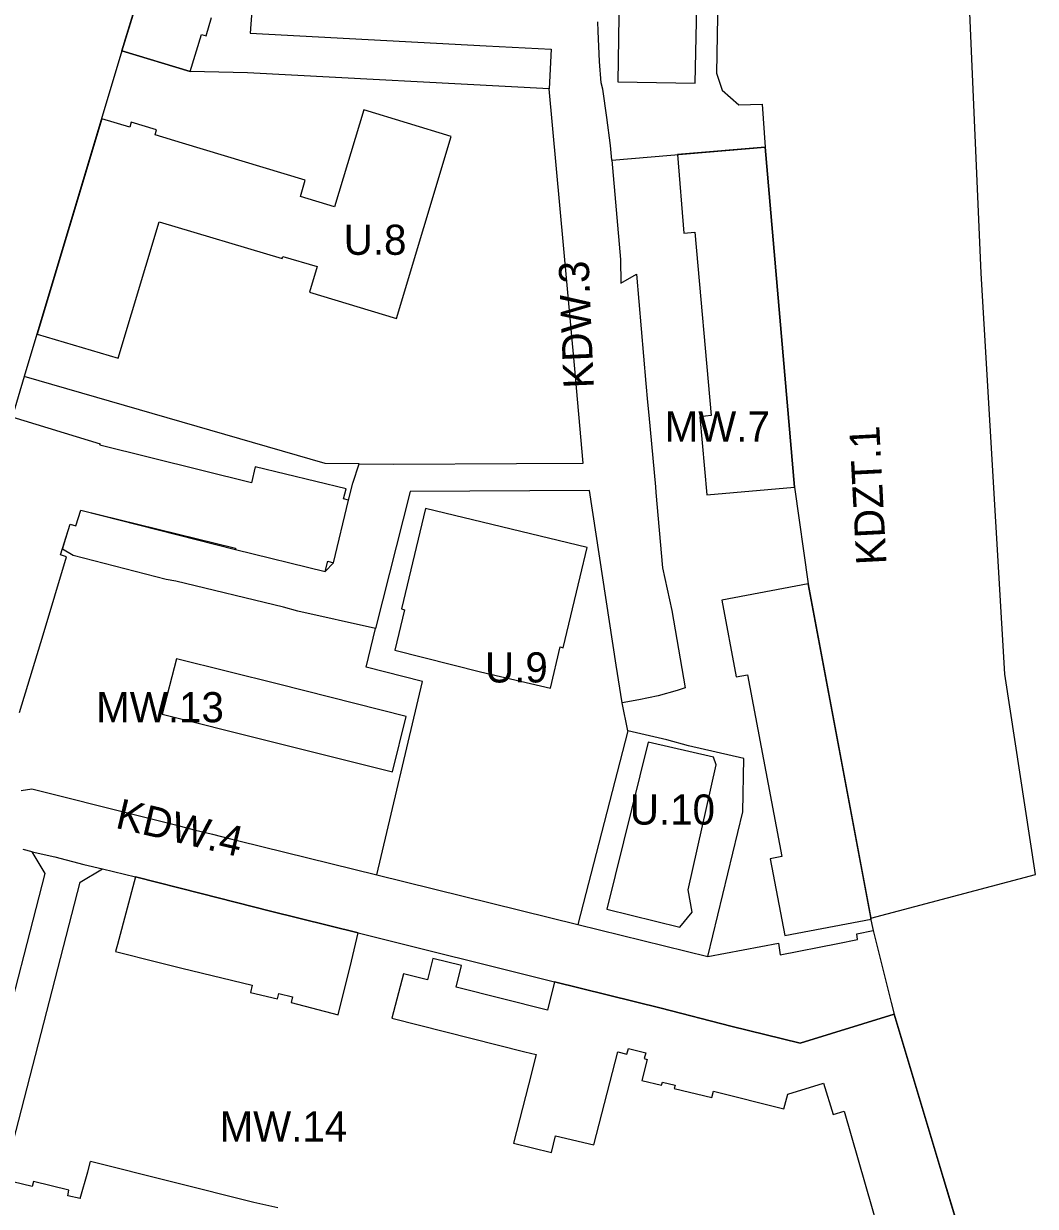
# Model space of a CAD drawing. Extents: x 7424052 to 7425705, y 5546602 to 5547569.
# Drawn here: x 7425299.9 to 7425467.7, y 5547085.1 to 5547281.2 of the extents above; entities that cross this region are included whole.
import ezdxf

# ---------------------------------------------------------------- set-up
doc = ezdxf.new("R2010")
doc.units = 0
for name, color, linetype in [('linie rozgraniczające', 7, 'Continuous'), ('nieprzekraczalne linie zabudowy', 7, 'Continuous'), ('obowiazujace linie zabudowy', 7, 'Continuous'), ('przeznaczenia terenów', 7, 'Continuous')]:
    doc.layers.add(name, color=color, linetype=linetype)

msp = doc.modelspace()

# ---------------------------------------------------------------- linework, layer by layer
at = {"layer": 'linie rozgraniczające'}
for p, q in [((7425415.3, 5547303.98), (7425414.81, 5547272.98)), ((7425458.68, 5547239.81), (7425456.07, 5547299.57)), ((7425316.21, 5547276.67), (7425320.91, 5547292.15)), ((7425338.05, 5547287.8), (7425337.46, 5547279.59)), ((7425395.16, 5547279.91), (7425395.12, 5547281.49)), ((7425337.46, 5547279.59), (7425357.04, 5547278.55)), ((7425395.38, 5547274.88), (7425395.16, 5547279.91)), ((7425357.04, 5547278.55), (7425376.62, 5547277.51)), ((7425376.62, 5547277.51), (7425387.4, 5547276.93)), ((7425316.21, 5547276.67), (7425299.97, 5547222.7)), ((7425327.5, 5547273.25), (7425316.21, 5547276.67)), ((7425387.4, 5547276.93), (7425387.04, 5547270.36)), ((7425337.05, 5547273.02), (7425327.5, 5547273.25)), ((7425395.7, 5547271.39), (7425395.38, 5547274.88)), ((7425387.04, 5547270.36), (7425337.05, 5547273.02)), ((7425395.96, 5547270.3), (7425395.7, 5547271.39)), ((7425414.81, 5547272.98), (7425415.74, 5547270.16)), ((7425391.23, 5547224.55), (7425387.04, 5547270.36)), ((7425396.59, 5547265.64), (7425395.96, 5547270.3)), ((7425415.74, 5547270.16), (7425418.49, 5547267.7)), ((7425418.49, 5547267.7), (7425422.39, 5547267.81)), ((7425422.39, 5547267.81), (7425422.85, 5547260.69)), ((7425397.22, 5547260.99), (7425396.59, 5547265.64)), ((7425397.43, 5547258.56), (7425397.22, 5547260.99)), ((7425397.43, 5547258.56), (7425422.85, 5547260.69)), ((7425422.85, 5547260.69), (7425427.73, 5547204.35)), ((7425397.43, 5547258.56), (7425398.88, 5547242.07)), ((7425398.88, 5547242.07), (7425398.96, 5547238.14)), ((7425462.6, 5547173.31), (7425458.68, 5547239.81)), ((7425398.96, 5547238.14), (7425401.52, 5547239.64)), ((7425401.52, 5547239.64), (7425403.11, 5547221.51)), ((7425392.71, 5547208.29), (7425391.23, 5547224.55)), ((7425299.97, 5547222.7), (7425297.97, 5547215.91)), ((7425349.9, 5547208.27), (7425299.97, 5547222.7)), ((7425403.11, 5547221.51), (7425403.37, 5547218.42)), ((7425403.37, 5547218.42), (7425403.57, 5547216.26)), ((7425403.57, 5547216.26), (7425404.68, 5547204.38)), ((7425355.56, 5547208.2), (7425349.9, 5547208.27)), ((7425354.52, 5547204.97), (7425355.56, 5547208.2)), ((7425355.56, 5547208.2), (7425361.22, 5547208.13)), ((7425361.22, 5547208.13), (7425381.62, 5547208.22)), ((7425381.62, 5547208.22), (7425392.71, 5547208.29)), ((7425353.79, 5547202.16), (7425354.52, 5547204.97)), ((7425364.02, 5547203.61), (7425358.27, 5547180.87)), ((7425393.75, 5547203.76), (7425364.02, 5547203.61)), ((7425398.18, 5547174.83), (7425393.75, 5547203.76)), ((7425404.68, 5547204.38), (7425404.75, 5547203.42)), ((7425404.75, 5547203.42), (7425405.85, 5547190.96)), ((7425427.73, 5547204.35), (7425430.02, 5547188.31)), ((7425351.26, 5547191.8), (7425353.79, 5547202.16)), ((7425308.58, 5547197.9), (7425309.4, 5547200.52)), ((7425309.4, 5547200.52), (7425335.02, 5547194)), ((7425306.32, 5547194.06), (7425307.27, 5547197.12)), ((7425307.27, 5547197.12), (7425307.59, 5547198.21)), ((7425307.59, 5547198.21), (7425308.58, 5547197.9)), ((7425308.13, 5547193.02), (7425306.32, 5547194.06)), ((7425323.56, 5547189.01), (7425308.13, 5547193.02)), ((7425335.02, 5547194), (7425349.92, 5547190.36)), ((7425349.92, 5547190.36), (7425351.26, 5547191.8)), ((7425405.85, 5547190.96), (7425407.39, 5547183.85)), ((7425325.16, 5547188.75), (7425323.56, 5547189.01)), ((7425342.99, 5547184.4), (7425325.16, 5547188.75)), ((7425430.02, 5547188.31), (7425440.41, 5547132.88)), ((7425345.38, 5547183.76), (7425342.99, 5547184.4)), ((7425358.27, 5547180.87), (7425345.38, 5547183.76)), ((7425407.39, 5547183.85), (7425409.59, 5547171.04)), ((7425356.73, 5547174.45), (7425358.27, 5547180.87)), ((7425366.03, 5547172.1), (7425356.73, 5547174.45)), ((7425399.17, 5547168.56), (7425398.18, 5547174.83)), ((7425467.68, 5547140.09), (7425462.6, 5547173.31)), ((7425358.46, 5547140.05), (7425366.03, 5547172.1)), ((7425405.15, 5547169.73), (7425401.9, 5547169.04)), ((7425408.26, 5547170.61), (7425405.15, 5547169.73)), ((7425409.59, 5547171.04), (7425408.26, 5547170.61)), ((7425401.9, 5547169.04), (7425399.17, 5547168.56)), ((7425400.08, 5547163.91), (7425399.17, 5547168.56)), ((7425400.08, 5547163.91), (7425391.82, 5547131.78)), ((7425406.59, 5547162.41), (7425400.08, 5547163.91)), ((7425410.18, 5547161.43), (7425406.59, 5547162.41)), ((7425419.34, 5547159.35), (7425410.18, 5547161.43)), ((7425419.16, 5547150.49), (7425419.34, 5547159.35)), ((7425299.48, 5547154.02), (7425301.26, 5547154.33)), ((7425301.26, 5547154.33), (7425318.66, 5547149.93)), ((7425318.66, 5547149.93), (7425321.96, 5547149.09)), ((7425413.34, 5547126.51), (7425419.16, 5547150.49)), ((7425321.96, 5547149.09), (7425325.06, 5547148.31)), ((7425325.06, 5547148.31), (7425328.17, 5547147.52)), ((7425328.17, 5547147.52), (7425331.22, 5547146.76)), ((7425331.22, 5547146.76), (7425334.42, 5547145.95)), ((7425334.42, 5547145.95), (7425335.56, 5547145.67)), ((7425335.56, 5547145.67), (7425358.46, 5547140.05)), ((7425301.29, 5547143.88), (7425299.83, 5547144.23)), ((7425303.47, 5547140.29), (7425301.29, 5547143.88)), ((7425301.29, 5547143.88), (7425305.05, 5547143)), ((7425305.05, 5547143), (7425309.86, 5547141.77)), ((7425309.86, 5547141.77), (7425312.95, 5547141.02)), ((7425294.16, 5547104.2), (7425303.47, 5547140.29)), ((7425309.28, 5547138.82), (7425312.95, 5547141.02)), ((7425312.95, 5547141.02), (7425318.43, 5547139.69)), ((7425358.46, 5547140.05), (7425391.82, 5547131.78)), ((7425440.41, 5547132.88), (7425467.68, 5547140.09)), ((7425297.73, 5547094.02), (7425309.28, 5547138.82)), ((7425318.43, 5547139.69), (7425329.36, 5547136.96)), ((7425329.36, 5547136.96), (7425340.86, 5547134.01)), ((7425340.86, 5547134.01), (7425355.4, 5547130.4)), ((7425355.4, 5547130.4), (7425387.95, 5547122.28)), ((7425391.82, 5547131.78), (7425413.34, 5547126.51)), ((7425438.07, 5547130.24), (7425440.79, 5547130.79)), ((7425438.19, 5547129.32), (7425438.07, 5547130.24)), ((7425413.34, 5547126.51), (7425425.06, 5547128.72)), ((7425425.06, 5547128.72), (7425425.35, 5547126.78)), ((7425425.35, 5547126.78), (7425434.91, 5547128.67)), ((7425434.91, 5547128.67), (7425438.19, 5547129.32)), ((7425387.95, 5547122.28), (7425405.6, 5547117.92)), ((7425443.78, 5547118.87), (7425444.26, 5547116.94)), ((7425405.6, 5547117.92), (7425417.19, 5547114.97)), ((7425428.7, 5547112.14), (7425444.26, 5547116.94)), ((7425417.19, 5547114.97), (7425428.7, 5547112.14))]:
    msp.add_line(p, q, dxfattribs=at)
for points in [[(7425440.41, 5547132.88), (7425440.34, 5547132.86), (7425440.57, 5547131.82), (7425440.79, 5547130.79), (7425440.79, 5547130.79)], [(7425440.79, 5547130.79), (7425442.29, 5547124.83), (7425443.78, 5547118.87)], [(7425444.26, 5547116.94), (7425452.42, 5547089.88), (7425460.58, 5547062.82)]]:
    msp.add_lwpolyline(points, dxfattribs=at)
at = {"layer": 'nieprzekraczalne linie zabudowy'}
for p, q in [((7425366.55, 5547200.79), (7425362.54, 5547184.14)), ((7425393.37, 5547194.31), (7425366.55, 5547200.79)), ((7425392.21, 5547189.45), (7425393.37, 5547194.31)), ((7425389.4, 5547177.7), (7425392.21, 5547189.45)), ((7425363.07, 5547184.01), (7425361.48, 5547177.32)), ((7425362.54, 5547184.14), (7425363.07, 5547184.01)), ((7425361.48, 5547177.32), (7425375.64, 5547173.73)), ((7425387.25, 5547170.99), (7425388.87, 5547177.83)), ((7425388.87, 5547177.83), (7425389.4, 5547177.7)), ((7425325.27, 5547175.85), (7425322.89, 5547166.67)), ((7425342.17, 5547171.64), (7425325.27, 5547175.85)), ((7425375.64, 5547173.73), (7425387.25, 5547170.99)), ((7425363.34, 5547166.28), (7425342.17, 5547171.64)), ((7425322.89, 5547166.67), (7425339.83, 5547162.42)), ((7425361.06, 5547157.1), (7425363.34, 5547166.28)), ((7425339.83, 5547162.42), (7425361.06, 5547157.1)), ((7425403.48, 5547162.06), (7425396.59, 5547134.35)), ((7425414.3, 5547159.54), (7425403.48, 5547162.06)), ((7425414.76, 5547158.28), (7425414.3, 5547159.54)), ((7425410.11, 5547137.53), (7425414.76, 5547158.28)), ((7425410.79, 5547133.83), (7425410.11, 5547137.53)), ((7425396.59, 5547134.35), (7425408.73, 5547131.37)), ((7425408.73, 5547131.37), (7425410.79, 5547133.83))]:
    msp.add_line(p, q, dxfattribs=at)
at = {"layer": 'obowiazujace linie zabudowy'}
for p, q in [((7425367.77, 5547126.19), (7425366.88, 5547122.62)), ((7425372.54, 5547125.01), (7425367.77, 5547126.19)), ((7425371.65, 5547121.41), (7425372.54, 5547125.01)), ((7425362.89, 5547123.61), (7425360.98, 5547116.3)), ((7425366.88, 5547122.62), (7425362.89, 5547123.61)), ((7425387.95, 5547122.28), (7425386.75, 5547117.59)), ((7425405.6, 5547117.92), (7425387.95, 5547122.28)), ((7425386.75, 5547117.59), (7425371.65, 5547121.41)), ((7425360.98, 5547116.3), (7425383.02, 5547110.69)), ((7425417.19, 5547114.97), (7425405.6, 5547117.92)), ((7425444.26, 5547116.94), (7425428.7, 5547112.14)), ((7425452.42, 5547089.88), (7425444.26, 5547116.94)), ((7425428.7, 5547112.14), (7425417.19, 5547114.97)), ((7425383.02, 5547110.69), (7425384.89, 5547110.27)), ((7425394.46, 5547095.29), (7425398.42, 5547110.68)), ((7425398.42, 5547110.68), (7425399.94, 5547110.31)), ((7425399.94, 5547110.31), (7425400.19, 5547111.26)), ((7425400.19, 5547111.26), (7425403.07, 5547110.53)), ((7425403.07, 5547110.53), (7425402.83, 5547109.58)), ((7425384.89, 5547110.27), (7425383.6, 5547105.23)), ((7425403.33, 5547109.43), (7425402.4, 5547105.95)), ((7425402.83, 5547109.58), (7425403.33, 5547109.43)), ((7425383.6, 5547105.23), (7425381.12, 5547095.53)), ((7425402.4, 5547105.95), (7425405.7, 5547105.15)), ((7425405.7, 5547105.15), (7425405.84, 5547105.69)), ((7425405.84, 5547105.69), (7425407.93, 5547105.19)), ((7425407.93, 5547105.19), (7425407.8, 5547104.64)), ((7425407.8, 5547104.64), (7425414.03, 5547103.1)), ((7425426.65, 5547103.68), (7425432.56, 5547105.48)), ((7425432.56, 5547105.48), (7425434.13, 5547100.32)), ((7425414.03, 5547103.1), (7425414.33, 5547104.17)), ((7425414.33, 5547104.17), (7425425.98, 5547101.23)), ((7425425.98, 5547101.23), (7425426.65, 5547103.68)), ((7425434.13, 5547100.32), (7425435.97, 5547100.84)), ((7425435.97, 5547100.84), (7425444.5, 5547071.39)), ((7425387.46, 5547094.01), (7425388.12, 5547096.77)), ((7425388.12, 5547096.77), (7425394.46, 5547095.29)), ((7425381.12, 5547095.53), (7425387.46, 5547094.01)), ((7425460.58, 5547062.82), (7425452.42, 5547089.88))]:
    msp.add_line(p, q, dxfattribs=at)
for points in [[(7425320.91, 5547292.15), (7425316.21, 5547276.67), (7425327.5, 5547273.25), (7425329.4, 5547279.38), (7425330.15, 5547279.17), (7425331.04, 5547282.19)], [(7425398.65, 5547285.99), (7425398.46, 5547271.56), (7425411.28, 5547271.31), (7425411.64, 5547289.21)], [(7425342.79, 5547242.23), (7425342.89, 5547242.59), (7425348.55, 5547240.89), (7425347.29, 5547236.66), (7425361.72, 5547232.28), (7425370.81, 5547262.47), (7425356.3, 5547266.87), (7425351.47, 5547250.79), (7425345.79, 5547252.5), (7425346.59, 5547255.25), (7425326.24, 5547261.38), (7425321.69, 5547262.72), (7425321.91, 5547263.59), (7425317.74, 5547264.82), (7425317.49, 5547263.99), (7425312.85, 5547265.38), (7425302.14, 5547229.69), (7425315.59, 5547225.73), (7425322.37, 5547248.34), (7425342.79, 5547242.23)], [(7425408.31, 5547259.47), (7425409.4, 5547246.46), (7425411.22, 5547246.63), (7425413.91, 5547216.22), (7425412.05, 5547215.99), (7425413.21, 5547203.04), (7425427.73, 5547204.35), (7425422.85, 5547260.69), (7425408.31, 5547259.47)], [(7425306.01, 5547193.08), (7425307.27, 5547197.12), (7425307.59, 5547198.21), (7425308.58, 5547197.9), (7425309.4, 5547200.52), (7425335.03, 5547194.23), (7425335.02, 5547194), (7425349.92, 5547190.36), (7425350.33, 5547192.04), (7425351.26, 5547191.8), (7425353.79, 5547202.16), (7425352.95, 5547202.37), (7425353.36, 5547204.03), (7425338.32, 5547207.7), (7425337.66, 5547205.06), (7425312.55, 5547211.26), (7425312.62, 5547211.48), (7425297.97, 5547215.91)], [(7425299.23, 5547166.94), (7425303.12, 5547179.86), (7425307, 5547192.79), (7425306.01, 5547193.08)], [(7425306.01, 5547193.08), (7425306.01, 5547193.08)], [(7425415.7, 5547185.59), (7425418.09, 5547172.85), (7425419.94, 5547173.21), (7425425.63, 5547143.07), (7425423.73, 5547142.7), (7425426.11, 5547129.98), (7425440.45, 5547132.69), (7425430.02, 5547188.31), (7425415.7, 5547185.59)], [(7425354.26, 5547125.75), (7425355.4, 5547130.4), (7425340.86, 5547134.01), (7425329.36, 5547136.96), (7425318.43, 5547139.69), (7425315.45, 5547128.51), (7425315.13, 5547127.33), (7425322.18, 5547125.54), (7425326.13, 5547124.56), (7425337.8, 5547121.73), (7425337.51, 5547120.55), (7425341.99, 5547119.46), (7425342.23, 5547120.39), (7425344.48, 5547119.8), (7425344.26, 5547118.88), (7425352.06, 5547116.82), (7425354.26, 5547125.75)], [(7425309.25, 5547086.36), (7425307.2, 5547086.84), (7425307.37, 5547087.76), (7425301.55, 5547089.21), (7425301.31, 5547088.34), (7425291.44, 5547090.76), (7425291.59, 5547091.7), (7425285.84, 5547093.13), (7425285.59, 5547092.24), (7425275.72, 5547094.71), (7425275.92, 5547095.64), (7425270.15, 5547097.05), (7425269.97, 5547096.24), (7425264.11, 5547097.66), (7425262.75, 5547092.29), (7425262.55, 5547092.33), (7425262.45, 5547091.94), (7425262.63, 5547091.89), (7425261.47, 5547087.26), (7425261.25, 5547087.29), (7425261.14, 5547086.81), (7425267.78, 5547085.24), (7425268.05, 5547086.33), (7425304.7, 5547077.14)], [(7425309.25, 5547086.36), (7425310.54, 5547090.81), (7425310.96, 5547092.52)], [(7425342.05, 5547084.81), (7425338.1, 5547085.73), (7425310.96, 5547092.52)]]:
    msp.add_lwpolyline(points, dxfattribs=at)

# ---------------------------------------------------------------- texts
at = {"layer": 'przeznaczenia terenów'}
for s, p in [('U.8', (7425352.98, 5547242.85)), ('MW.7', (7425406.2, 5547211.89)), ('U.9', (7425376.42, 5547171.94)), ('MW.13', (7425311.93, 5547165.34)), ('U.10', (7425400.43, 5547148.37)), ('MW.14', (7425332.39, 5547095.82))]:
    msp.add_text(s, height=5, dxfattribs=at).set_placement(p)
for s, rotation, p in [('KDW.3', 92.3246, (7425394.46, 5547220.79)), ('KDZT.1', 93, (7425443, 5547191.57)), ('KDW.4', 346.6976, (7425314.94, 5547147.87))]:
    msp.add_text(s, height=5, rotation=rotation, dxfattribs=at).set_placement(p)

doc.saveas('drawing.dxf')
